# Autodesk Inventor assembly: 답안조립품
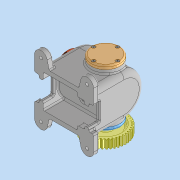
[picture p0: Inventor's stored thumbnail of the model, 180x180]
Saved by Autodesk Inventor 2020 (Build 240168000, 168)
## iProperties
Created: 2024-09
Part Number: 답안조립품
Document SubType Name: Assembly
Designer: oem
Author: oem
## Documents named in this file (17)
- C:\Users\oem\Desktop\740904V1013\답안조립품.iam
- C:\Users\oem\Desktop\740904V1013\본체.ipt
- C:\Users\oem\Desktop\740904V1013\640804V1002\깊은 홈 볼베어링 6203.ipt
- C:\Users\oem\Desktop\740904V1013\640804V1002\뒷커버.ipt
- C:\Users\oem\Desktop\740904V1013\640804V1002\로드.ipt
- C:\Users\oem\Desktop\740904V1013\640804V1002\부시.ipt
- C:\Users\oem\Desktop\740904V1013\640804V1002\스퍼 기어.ipt
- C:\Users\oem\Desktop\740904V1013\640804V1002\스프링와셔 M10.ipt
- C:\Users\oem\Desktop\740904V1013\640804V1002\실링 패드.ipt
- C:\Users\oem\Desktop\740904V1013\640804V1002\앞커버.ipt
- C:\Users\oem\Desktop\740904V1013\640804V1002\오일실 17 32 8.ipt
- C:\Users\oem\Desktop\740904V1013\640804V1002\육각 너트 M10x1.ipt
- C:\Users\oem\Desktop\740904V1013\640804V1002\육각 머리 볼트 M6x0.75x12.ipt
- C:\Users\oem\Desktop\740904V1013\640804V1002\육각 소켓 머리 볼트 M4x10.ipt
- C:\Users\oem\Desktop\740904V1013\640804V1002\편심축.ipt
- C:\Users\oem\Desktop\740904V1013\640804V1002\평와셔 M10.ipt
- C:\Users\oem\Desktop\740904V1013\640804V1002\평행키 3x3x14.ipt
